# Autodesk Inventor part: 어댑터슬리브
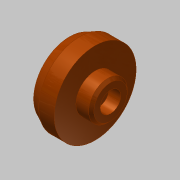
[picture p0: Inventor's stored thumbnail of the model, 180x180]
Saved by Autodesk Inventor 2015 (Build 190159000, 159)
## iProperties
Created: 2016-06
Part Number: 어댑터슬리브
Material: 강철, 탄소
Document SubType Name: Modeling
Designer: mduedu
Density: 7.87 g/cm^3
Appearance: 매끄러움 - 연한 주황색
Author: mduedu
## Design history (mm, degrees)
sketch "스케치2"
  geometry: L1 (0, 0)-(0, 14); L2 (0, 14)-(-4, 16); L3 (-4, 16)-(-10, 16); L4 (-10, 16)-(-10, 7.5); L5 (-10, 7.5)-(-16, 7.5); L6 (-16, 7.5)-(-16, 0); L7 (-16, 0)-(0, 0)
  constraints: 14 end point, 4 parallel, 1 perpendicular, 1 vertical
  dimensions: "d0" = 32 diameter of L3 L7; "d2" = 28 diameter of L1.end L7; "d3" = 6 distance of L2.end L3.end; "d4" = 6 distance of L4.end L5.end; "d5" = 15 diameter of L5 L7; "d6" = 16 distance between parallel lines of L6 L1
revolve "회전1" sketch "스케치2" stored, may be unused: angle "d7" = 90 deg
sketch "스케치3"
  geometry: L1 (-16, -7.5)-(-16, 7.5) reference; L2 (-16, 7.5)-(-10, 7.5) reference; L3 (-10, 7.5)-(-10, 16) reference; L4 (-10, 16)-(-4, 16) reference; L5 (-4, 16)-(0, 14) reference; L6 (0, 14)-(0, -14) reference; L7 (0, -14)-(-4, -16) reference; L8 (-4, -16)-(-10, -16) reference; L9 (-10, -16)-(-10, -7.5) reference; L10 (-10, -7.5)-(-16, -7.5) reference; L11 (0, 10)-(-5, 10); L12 (-5, 10)-(-5, 8); L13 (-5, 8)-(-7, 6); L14 (-7, 6)-(-7, 0); L15 (-7, 0)-(0, 0); L16 (0, 10)-(0, 0)
  constraints: 12 end point, 3 parallel, 2 perpendicular, 1 point on line
  dimensions: "d8" = 20 diameter of L11 L15; "d10" = 16 diameter of L12.end L15; "d11" = 12 diameter of L13.end L15; "d12" = 9 distance between parallel lines of L14 L1; "d13" = 2 distance between parallel lines of L12 L14
revolve "회전2" sketch "스케치3" stored, may be unused: angle "d14" = 90 deg
chamfer "모따기1" distance "d15" = 1; stored, may be unused: second distance "d16" = 2, angle "d17" = 45 deg
sketch "스케치4"
  geometry: 2 further points
  constraints: 1 coincident
sketch "스케치5"
  geometry: 1 further point
hole "구멍1" sketch "스케치5" at (0, 0) diameter "d18" = 4.5; stored, may be unused: countersink angle "d22" = 90 deg, drill point angle "d24" = 0 deg; dims "d19" = 6, "d20" = 8, "d21" = 4.6, "d23" = 8
node "솔리드1"
node "절단 모서리 투영1"
